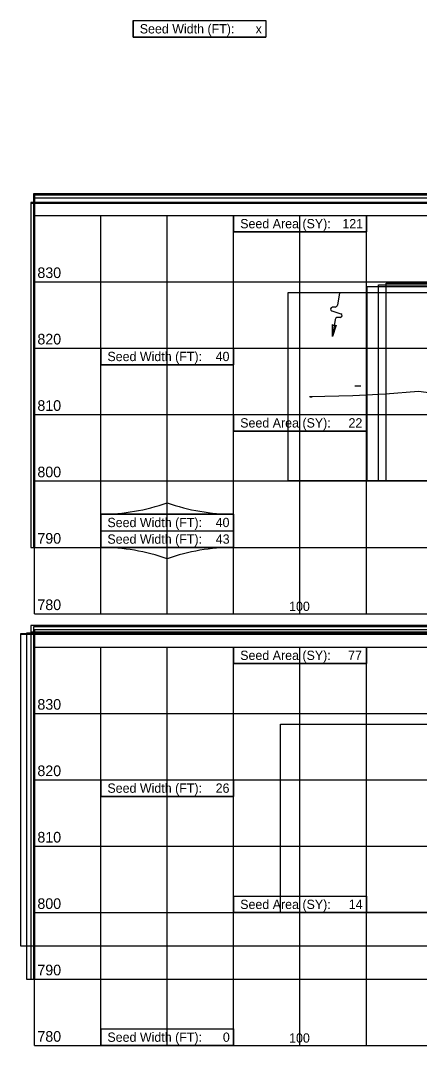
# Model space of a CAD drawing. Extents: x -475 to 76, y 0 to 417.
# Drawn here: x -472.81 to -466.81, y 374.16 to 389.6 of the extents above; entities that cross this region are included whole.
import ezdxf

# ---------------------------------------------------------------- set-up
doc = ezdxf.new("R2010")
doc.units = 0
for name, color, linetype in [('_CIVIL_CONSTRUCTION', 7, 'Continuous'), ('Default', 7, 'Continuous'), ('RW_P_Esmt_TMP', 7, 'Continuous'), ('SC_Scratch1', 7, 'Continuous'), ('SC_Scratch10', 7, 'Continuous'), ('SH_Masking', 7, 'Continuous'), ('SV_P_Mon_Cells_Set', 7, 'Continuous'), ('SV_X_Break_Lines', 7, 'Continuous'), ('SV_X_Random_Point', 7, 'Continuous'), ('SV_X_Shot_Marker', 7, 'Continuous')]:
    doc.layers.add(name, color=color, linetype=linetype)

msp = doc.modelspace()

# ---------------------------------------------------------------- linework, layer by layer
at = {"layer": '_CIVIL_CONSTRUCTION'}
for points in [[(-472.619, 381.665), (-444.621, 381.665), (-444.621, 386.989), (-472.619, 386.989)], [(-472.619, 381.665), (-444.621, 381.665), (-444.621, 386.989), (-472.619, 386.989)], [(-472.606, 381.665), (-444.606, 381.665), (-444.606, 386.968), (-472.606, 386.968)], [(-472.658, 381.665), (-444.665, 381.665), (-444.665, 386.856), (-472.658, 386.856)], [(-472.658, 381.665), (-444.665, 381.665), (-444.665, 386.856), (-472.658, 386.856)], [(-472.657, 381.665), (-458.66, 381.665), (-458.66, 386.845), (-472.657, 386.845)], [(-472.657, 381.665), (-458.66, 381.665), (-458.66, 386.845), (-472.657, 386.845)], [(-472.619, 381.665), (-444.621, 381.665), (-444.621, 386.923), (-472.619, 386.923)], [(-472.619, 381.665), (-444.621, 381.665), (-444.621, 386.923), (-472.619, 386.923)], [(-460.212, 382.665), (-467.596, 382.665), (-467.596, 385.592), (-460.212, 385.592)], [(-460.042, 382.665), (-467.426, 382.665), (-467.426, 385.618), (-460.042, 385.618)], [(-459.921, 382.665), (-467.306, 382.665), (-467.306, 385.642), (-459.921, 385.642)], [(-461.401, 382.665), (-468.786, 382.665), (-468.786, 385.504), (-461.401, 385.504)], [(-472.658, 375.165), (-444.665, 375.165), (-444.665, 380.489), (-472.658, 380.489)], [(-472.658, 375.165), (-444.665, 375.165), (-444.665, 380.489), (-472.658, 380.489)], [(-472.619, 375.165), (-444.621, 375.165), (-444.621, 380.468), (-472.619, 380.468)], [(-472.619, 375.165), (-444.621, 375.165), (-444.621, 380.468), (-472.619, 380.468)], [(-472.815, 375.665), (-444.842, 375.665), (-444.842, 380.364), (-472.815, 380.364)], [(-472.815, 375.665), (-444.842, 375.665), (-444.842, 380.364), (-472.815, 380.364)], [(-472.815, 375.665), (-444.842, 375.665), (-444.842, 380.354), (-472.815, 380.354)], [(-472.815, 375.665), (-444.842, 375.665), (-444.842, 380.354), (-472.815, 380.354)], [(-472.724, 375.665), (-444.739, 375.665), (-444.739, 380.371), (-472.724, 380.371)], [(-472.724, 375.665), (-444.739, 375.665), (-444.739, 380.371), (-472.724, 380.371)], [(-472.724, 375.165), (-444.739, 375.165), (-444.739, 380.356), (-472.724, 380.356)], [(-472.724, 375.165), (-444.739, 375.165), (-444.739, 380.356), (-472.724, 380.356)], [(-472.658, 375.665), (-444.665, 375.665), (-444.665, 380.389), (-472.658, 380.389)], [(-472.658, 375.665), (-444.665, 375.665), (-444.665, 380.389), (-472.658, 380.389)], [(-472.606, 375.165), (-444.606, 375.165), (-444.606, 380.423), (-472.606, 380.423)], [(-461.385, 376.165), (-468.901, 376.165), (-468.901, 379.004), (-461.385, 379.004)]]:
    msp.add_lwpolyline(points, close=True, dxfattribs=at)
at = {"layer": 'Default'}
for p, q in [((-468.013, 385.497), (-468.042, 385.314)), ((-468.078, 385.282), (-468.119, 385.281)), ((-468.126, 385.226), (-467.992, 385.184)), ((-468.076, 385.096), (-468.116, 384.843)), ((-468, 385.129), (-468.04, 385.128)), ((-468.116, 384.843), (-468.118, 385.019)), ((-468.118, 385.019), (-468.118, 385.019)), ((-468.061, 385.01), (-468.116, 384.843)), ((-468.061, 385.01), (-468.061, 385.01))]:
    msp.add_line(p, q, dxfattribs=at)
for centre, radius, start, end in [((-468.118, 385.253), 0.0281, 91.689, 252.5386), ((-468.079, 385.32), 0.0375, 271.689, 351.0694), ((-468.039, 385.09), 0.0375, 91.689, 171.0694), ((-468.001, 385.157), 0.0281, 271.689, 72.5386), ((-468.082, 385.058), 0.0527, 227.2474, 293.9282)]:
    msp.add_arc(centre, radius, start, end, dxfattribs=at)
at = {"layer": 'RW_P_Esmt_TMP'}
for p, q in [((-472.606, 386.665), (-444.606, 386.665)), ((-472.606, 380.665), (-472.606, 386.665)), ((-472.606, 380.665), (-444.606, 380.665)), ((-472.606, 380.165), (-444.606, 380.165)), ((-472.606, 374.165), (-472.606, 380.165)), ((-472.606, 374.165), (-444.606, 374.165))]:
    msp.add_line(p, q, dxfattribs=at)
at = {"layer": 'SC_Scratch1'}
for p, q in [((-471.119, 389.599), (-469.119, 389.599)), ((-471.119, 389.599), (-471.119, 389.349)), ((-469.119, 389.599), (-469.119, 389.349)), ((-471.119, 389.349), (-469.119, 389.349)), ((-469.606, 386.665), (-467.606, 386.665)), ((-469.606, 386.665), (-469.606, 386.415)), ((-467.606, 386.665), (-467.606, 386.415)), ((-469.606, 386.415), (-467.606, 386.415)), ((-471.606, 384.665), (-469.606, 384.665)), ((-471.606, 384.665), (-471.606, 384.415)), ((-469.606, 384.665), (-469.606, 384.415)), ((-471.606, 384.415), (-469.606, 384.415)), ((-469.606, 383.665), (-467.606, 383.665)), ((-469.606, 383.665), (-469.606, 383.415)), ((-467.606, 383.665), (-467.606, 383.415)), ((-469.606, 383.415), (-467.606, 383.415)), ((-471.606, 382.165), (-469.606, 382.165)), ((-471.606, 382.165), (-471.606, 381.665)), ((-469.606, 382.165), (-471.606, 382.165)), ((-469.606, 382.165), (-469.606, 381.665)), ((-471.606, 381.915), (-469.606, 381.915)), ((-471.606, 381.665), (-469.606, 381.665)), ((-469.606, 381.665), (-471.606, 381.665)), ((-469.606, 380.165), (-467.606, 380.165)), ((-469.606, 380.165), (-469.606, 379.915)), ((-467.606, 380.165), (-467.606, 379.915)), ((-469.606, 379.915), (-467.606, 379.915)), ((-471.606, 378.165), (-469.606, 378.165)), ((-471.606, 378.165), (-471.606, 377.915)), ((-469.606, 378.165), (-469.606, 377.915)), ((-471.606, 377.915), (-469.606, 377.915)), ((-469.606, 376.415), (-467.606, 376.415)), ((-469.606, 376.415), (-469.606, 376.165)), ((-467.606, 376.415), (-467.606, 376.165)), ((-469.606, 376.165), (-467.606, 376.165)), ((-471.606, 374.415), (-469.606, 374.415)), ((-471.606, 374.415), (-471.606, 374.165)), ((-469.606, 374.415), (-469.606, 374.165)), ((-471.606, 374.165), (-469.606, 374.165))]:
    msp.add_line(p, q, dxfattribs=at)
for centre, start, end in [((-471.606, 385.165), 270, 289.4712), ((-469.606, 385.165), 250.5288, 270), ((-471.606, 378.665), 70.5288, 90), ((-469.606, 378.665), 90, 109.4712)]:
    msp.add_arc(centre, 3, start, end, dxfattribs=at)
at = {"layer": 'SH_Masking'}
for points in [[(-471.119, 389.599), (-469.119, 389.599), (-469.119, 389.349), (-471.119, 389.349)], [(-469.606, 386.665), (-467.606, 386.665), (-467.606, 386.415), (-469.606, 386.415)], [(-471.606, 384.665), (-469.606, 384.665), (-469.606, 384.415), (-471.606, 384.415)], [(-469.606, 383.665), (-467.606, 383.665), (-467.606, 383.415), (-469.606, 383.415)], [(-471.606, 382.165), (-469.606, 382.165), (-469.606, 381.665), (-471.606, 381.665)], [(-469.606, 380.165), (-467.606, 380.165), (-467.606, 379.915), (-469.606, 379.915)], [(-471.606, 378.165), (-469.606, 378.165), (-469.606, 377.915), (-471.606, 377.915)], [(-469.606, 376.415), (-467.606, 376.415), (-467.606, 376.165), (-469.606, 376.165)], [(-471.606, 374.415), (-469.606, 374.415), (-469.606, 374.165), (-471.606, 374.165)]]:
    msp.add_lwpolyline(points, close=True, dxfattribs=at)
at = {"layer": 'SV_P_Mon_Cells_Set'}
for p, q in [((-471.606, 380.665), (-471.606, 386.665)), ((-470.606, 380.665), (-470.606, 386.665)), ((-469.606, 380.665), (-469.606, 386.665)), ((-468.606, 380.665), (-468.606, 386.665)), ((-467.606, 380.665), (-467.606, 386.665)), ((-472.606, 385.665), (-455.42, 385.665)), ((-472.606, 384.665), (-460.806, 384.665)), ((-472.606, 383.665), (-461.986, 383.665)), ((-472.606, 382.665), (-444.606, 382.665)), ((-472.606, 381.665), (-444.606, 381.665)), ((-471.606, 374.165), (-471.606, 380.165)), ((-470.606, 374.165), (-470.606, 380.165)), ((-469.606, 374.165), (-469.606, 380.165)), ((-468.606, 374.165), (-468.606, 380.165)), ((-467.606, 374.165), (-467.606, 380.165)), ((-472.606, 379.165), (-455.506, 379.165)), ((-472.606, 378.165), (-460.677, 378.165)), ((-472.606, 377.165), (-444.606, 377.165)), ((-472.606, 376.165), (-444.606, 376.165)), ((-472.606, 375.165), (-444.606, 375.165))]:
    msp.add_line(p, q, dxfattribs=at)
at = {"layer": 'SV_X_Break_Lines'}
msp.add_lwpolyline([(-466.405, 383.958), (-466.823, 384.012), (-467.316, 383.974), (-467.808, 383.946), (-468.441, 383.93)], dxfattribs=at)
at = {"layer": 'SV_X_Random_Point'}
for p, q in [((-467.691, 384.094), (-467.781, 384.094)), ((-467.722, 384.094), (-467.751, 384.094))]:
    msp.add_line(p, q, dxfattribs=at)
at = {"layer": 'SV_X_Shot_Marker'}
for p, q in [((-468.418, 383.93), (-468.463, 383.93)), ((-468.452, 383.93), (-468.429, 383.93)), ((-468.441, 383.93), (-468.441, 383.93))]:
    msp.add_line(p, q, dxfattribs=at)

# ---------------------------------------------------------------- texts
at = {"layer": 'SC_Scratch10'}
for s, height, p in [('Seed Width (FT):', 0.14, (-471.019, 389.404)), ('x', 0.14, (-469.274, 389.404)), ('Seed Area (SY):', 0.14, (-469.506, 386.47)), ('121', 0.14, (-467.968, 386.47)), ('830', 0.16, (-472.56, 385.721)), ('820', 0.16, (-472.56, 384.721)), ('Seed Width (FT):', 0.14, (-471.506, 384.47)), ('40', 0.14, (-469.876, 384.47)), ('810', 0.16, (-472.56, 383.721)), ('Seed Area (SY):', 0.14, (-469.506, 383.47)), ('22', 0.14, (-467.875, 383.47)), ('800', 0.16, (-472.56, 382.721)), ('Seed Width (FT):', 0.14, (-471.506, 381.97)), ('40', 0.14, (-469.876, 381.97)), ('790', 0.16, (-472.56, 381.721)), ('Seed Width (FT):', 0.14, (-471.506, 381.72)), ('43', 0.14, (-469.874, 381.72)), ('780', 0.16, (-472.56, 380.721)), ('100', 0.14, (-468.77, 380.708)), ('Seed Area (SY):', 0.14, (-469.506, 379.97)), ('77', 0.14, (-467.882, 379.97)), ('830', 0.16, (-472.56, 379.221)), ('820', 0.16, (-472.56, 378.221)), ('Seed Width (FT):', 0.14, (-471.506, 377.97)), ('26', 0.14, (-469.876, 377.97)), ('810', 0.16, (-472.56, 377.221)), ('800', 0.16, (-472.56, 376.221)), ('Seed Area (SY):', 0.14, (-469.506, 376.22)), ('14', 0.14, (-467.872, 376.22)), ('790', 0.16, (-472.56, 375.221)), ('780', 0.16, (-472.56, 374.221)), ('Seed Width (FT):', 0.14, (-471.506, 374.22)), ('0', 0.14, (-469.767, 374.22)), ('100', 0.14, (-468.77, 374.208))]:
    msp.add_text(s, height=height, dxfattribs=at).set_placement(p)

doc.saveas('drawing.dxf')
